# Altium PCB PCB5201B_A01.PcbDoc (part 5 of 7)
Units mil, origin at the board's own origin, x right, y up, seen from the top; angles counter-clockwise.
Board outline 4527.56 x 2362.2 mil, 6 copper layers (Top Layer, GND Layer 2, Signal Layer 3, Signal Layer 4, VCC Layer 5, Bottom Layer), stack 61.221 mil thick; 361 components, 250 nets, 1223 pads, 1068 vias.
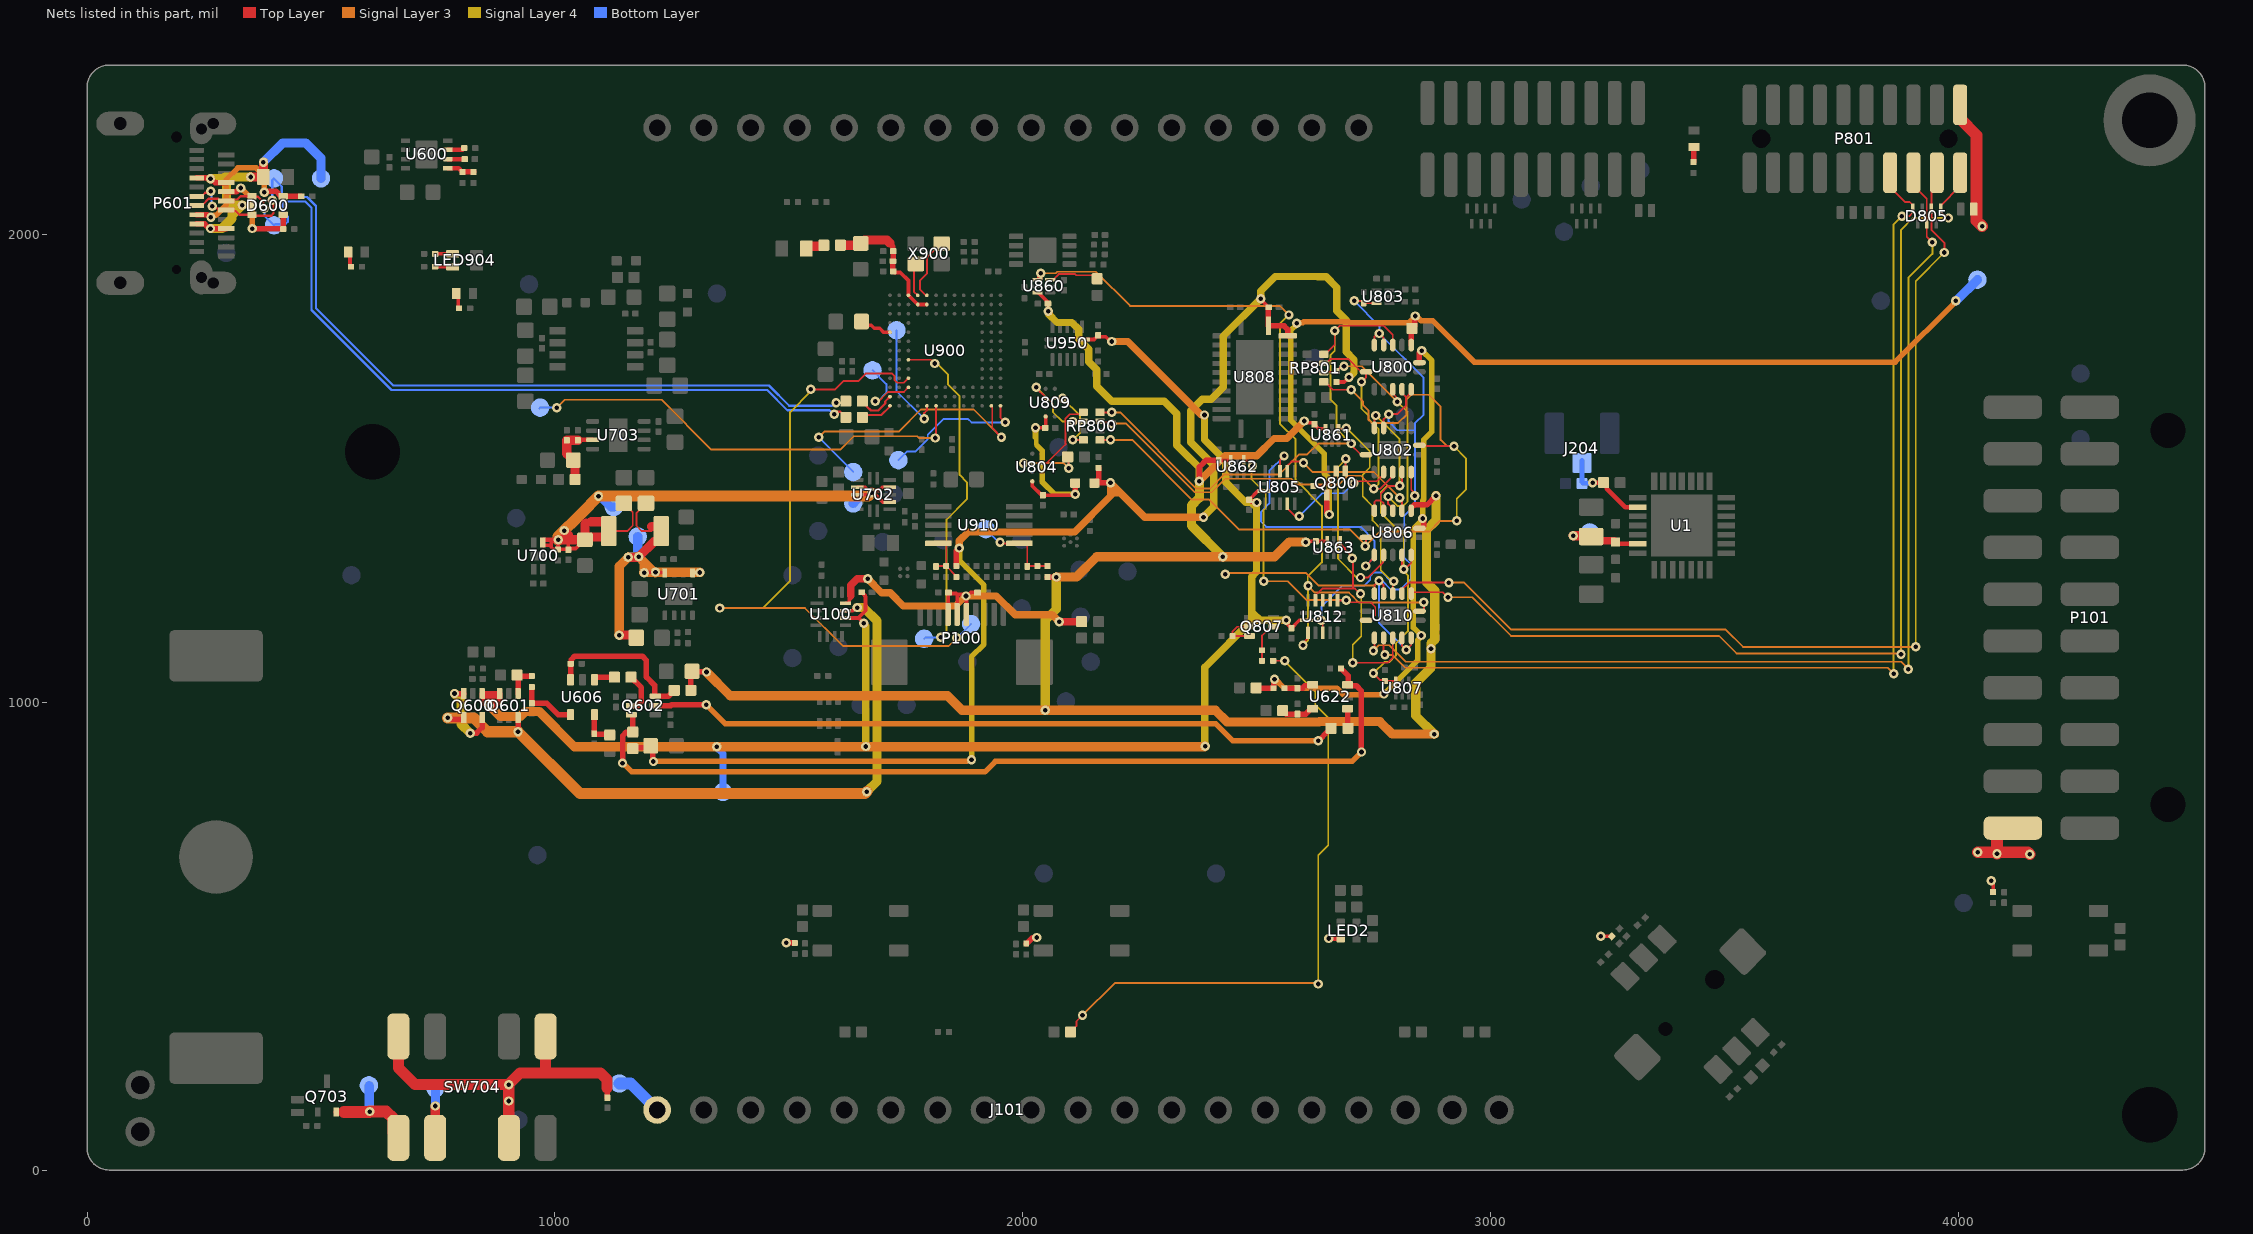
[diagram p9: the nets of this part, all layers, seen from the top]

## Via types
v1: diameter 20, hole 9.84, Top Layer to Bottom Layer, tented both sides, 1068 vias

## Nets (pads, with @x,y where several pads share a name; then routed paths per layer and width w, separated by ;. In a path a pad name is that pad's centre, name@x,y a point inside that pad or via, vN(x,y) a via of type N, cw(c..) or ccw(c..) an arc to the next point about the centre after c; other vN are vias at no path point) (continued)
N17517496: U802.10 U805.4 | length 264.9
  Top Layer w3.94: U805.4@2565.94,1424.61 2565.94,1414.37 2582.68,1397.64 v1(2591.54,1397.64) ; v1(2707.68,1468.5) 2711.61,1472.44 2747.08,1472.44 2756.86,1472.44 2771.65,1487.23 U802.10@2771.65,1492.13
  Bottom Layer w3.94: v1(2591.54,1397.64) 2640.75,1446.85 2686.02,1446.85 v1(2707.68,1468.5)
N17517567: R808.1 U802.6 U802.12 U806.5 U806.6 U806.12 U806.13 U807.3 | length 970.2
  Top Layer w3.94: v1(2750,1062.01) 2764.71,1047.3 2772.58,1047.3 R808.1@2774.61,1045.28 ; U806.6@2751.97,1409.45 2751.97,1428.15 2754.92,1431.1 2765.75,1431.1 ; U802.6@2751.97,1586.61 2752.43,1587.07 2752.43,1610.69 v1(2754.92,1613.19) ; U806.5@2771.65,1409.45 2771.65,1425.2 2765.75,1431.1 ; R808.1@2774.61,1044.29 2775.59,1045.28 2796.77,1045.28 U807.3@2797.76,1044.29 ; U806.12@2811.02,1314.96 2811.02,1292.73 2814.96,1288.8 v1(2814.96,1284.45) ; U802.12@2811.02,1492.13 2811.02,1467.52 v1(2806.1,1462.6) 2782.26,1462.6 2765.75,1446.09 2765.75,1431.1 ; v1@2814.96,1282.48 2830.71,1298.23 U806.13@2830.71,1314.96
  Signal Layer 4 w3.94: v1@2750,1063.98 2751.97,1063.98 2773.9,1085.91 2783.74,1085.91 2798.23,1100.39 2798.23,1125.98 2823.82,1151.57 2823.82,1271.24 2814.96,1280.1 v1(2814.96,1284.45) 2814.96,1356.3 2765.75,1405.51 2765.75,1448.82 2779.53,1462.6 v1(2806.1,1462.6) 2806.1,1562.01 v1(2754.92,1613.19)
N17517613: RP800.5 U804.C1 | length 166.8
  Top Layer w3.94: U804.C1@2040.35,1511.81 2052.17,1511.81 2091.54,1551.18 2091.54,1606.3 2091.82,1606.58 2091.82,1606.8 2100.88,1615.86 2125.71,1615.86 RP800.5@2129.92,1620.08
N17517626: RP800.6 U809.C2 | length 172.2
  Top Layer w3.94: v1(2029.37,1673.41) 2029.37,1671.82 2049.21,1651.98 U809.C2@2049.21,1650.59 ; v1(2107.28,1600.39) RP800.6@2129.92,1600.39
  Signal Layer 4 w3.94: v1(2029.37,1673.41) 2064.96,1637.83 2064.96,1620.08 2084.65,1600.39 v1(2107.28,1600.39)
N17517692: RP800.8 U809.C1 | length 150.2
  Top Layer w3.94: U809.C1@2068.9,1650.59 2069.11,1650.38 2084.97,1650.38 v1(2085.19,1650.16) ; v1(2107.28,1561.02) RP800.8@2129.92,1561.02
  Signal Layer 4 w3.94: v1(2085.19,1650.16) 2122.75,1612.6 2122.75,1576.49 v1(2107.28,1561.02)
N17517773: U805.9 U806.3 | length 317.4
  Top Layer w3.94: U805.9@2565.94,1494.29 2565.94,1505.91 2574.8,1514.76 2597.44,1514.76 v1(2600.39,1511.81) ; v1(2806.1,1437.01) 2811.02,1432.09 U806.3@2811.02,1409.45
  Signal Layer 3 w3.94: v1(2600.39,1511.81) 2620.08,1492.13 2751.21,1492.13 2806.1,1437.23 v1(2806.1,1437.01)
N17517791: U805.10 U806.9 | length 549.3
  Top Layer w3.94: U805.10@2550.2,1494.29 2550.2,1517.72 2558.94,1526.46 v1(2558.94,1526.69) ; v1(2733.27,1291.34) 2751.97,1310.04 U806.9@2751.97,1314.96
  Bottom Layer w3.94: v1(2558.94,1526.69) 2558.94,1526.46 2527.56,1495.08 2527.56,1425.2 2509.84,1407.48 2509.84,1385.83 2520.67,1375 2722.44,1375 2751.97,1345.47 2751.97,1310.04 v1(2733.27,1291.34)
N17517812: Q800.1 U806.10 | length 389.8
  Top Layer w3.94: Q800.1@2689.96,1494.09 2690.3,1494.43 2690.3,1520.02 v1(2690.83,1520.56) ; v1(2722.44,1266.73) 2738.19,1266.73 2770.68,1299.23 2770.68,1313.99 U806.10@2771.65,1314.96
  Signal Layer 4 w3.94: v1(2690.83,1520.56) 2690.83,1519.57 2674.21,1502.95 2674.21,1307.31 2714.79,1266.73 v1(2722.44,1266.73)
N17517960: R810.1 U804.C2 | length 147.4
  Top Layer w3.94: v1(2001.97,1511.32) 2002.46,1511.81 U804.C2@2020.67,1511.81 ; R810.1@2096.46,1524.61 2098.43,1522.64 v1(2098.43,1500)
  Signal Layer 3 w3.94: v1(2001.97,1511.32) 2088.09,1511.32 2099.41,1500 v1(2098.43,1500)
N17517966: Q800.2 R815.1 | length 65.8
  Top Layer w3.94: R815.1@2621.66,1462.29 2645.36,1462.29 2670.28,1487.2 Q800.2@2670.28,1494.09
N17518258: C804.1 C810.1 L801.2 U804.A2 U809.A2 | length 382.4
  Top Layer w7.87: U804.A2@2020.67,1472.44 2020.67,1462.6 2040.35,1442.91 C804.1@2043.31,1442.91 2110.24,1442.91 v1(2112.2,1444.88) ; v1(2027.56,1586.61) C810.1@2048.23,1586.61 2049.21,1587.6 U809.A2@2049.21,1611.22
  Top Layer w11.81: v1(2112.2,1444.88) L801.2@2112.21,1468.5
  Signal Layer 4 w9.84: 2027.56,1566.93 2029.53,1564.96 2029.53,1550.2 2031.5,1548.23
  Signal Layer 4 w11.81: 2027.56,1566.93 v1(2027.56,1586.61) ; 2031.5,1548.23 2042.32,1537.4 2042.32,1470.47 2067.91,1444.88 v1(2112.2,1444.88)
N17535327: U810.1 U812.1 U860.4 | length 1677.4
  Top Layer w3.94: U860.4@2031.5,1903.54 U860.4@2034.45,1903.54 ; v1(2599.41,1122.05) 2599.41,1126.97 2610.24,1137.8 U812.1@2610.24,1148.23 ; U810.1@2848.43,1194.88 2849.41,1195.87 2856.3,1195.87 2858.27,1197.83 2858.25,1212.9 v1(2857.56,1213.58)
  Top Layer w7.87: U860.4@2034.45,1903.54 U860.4@2036.42,1905.51
  Top Layer w11.81: U860.4@2036.42,1905.51 2036.42,1912.68 2039.13,1915.39 v1(2039.13,1917.6)
  Signal Layer 3 w3.94: v1(2039.13,1917.6) 2039.57,1917.16 2070.4,1917.16 2073.79,1920.56 2156.69,1920.56 2229.81,1847.44 2550.2,1847.44 2569.38,1828.26 v1(2569.38,1828.12) ; v1(2610.24,1249.02) 2624.72,1234.53 2697.78,1234.53 2708.94,1223.37 2708.94,1222.92 2718,1213.86 2718.45,1213.86 2718.73,1213.58 v1(2857.56,1213.58)
  Signal Layer 4 w3.94: v1(2569.38,1828.12) 2550.2,1808.94 2550.2,1595.47 2583.66,1562.01 2583.66,1475.39 2639.76,1419.29 2639.76,1299.21 2609.74,1269.19 2609.74,1249.51 v1(2610.24,1249.02) 2610.24,1132.87 v1(2599.41,1122.05)
N17535335: R882.1 U860.3 | length 109.5
  Top Layer w3.94: U860.3@2059.06,1903.54 2064.96,1903.54 2076.97,1915.55 2112.19,1915.55 2114.75,1912.99 2151.97,1912.99 R882.1@2159.45,1905.51
N17535359: U810.4 U812.3 U861.4 | length 686.4
  Top Layer w3.94: v1(2638.78,1175.2) 2641.73,1172.24 U812.3@2641.73,1148.23 ; U861.4@2675.2,1584.65 2693.9,1584.65 v1@2694.88,1585.63 ; U810.4@2791.34,1232.28 2791.34,1254.92 2793.31,1256.89 v1(2793.31,1258.86)
  Signal Layer 4 w3.94: v1(2691.93,1585.63) 2692.91,1585.63 2742.13,1536.42 2742.13,1501.97 2727.08,1486.93 2727.08,1440.24 2748.03,1419.29 2748.03,1388.78 2765.75,1371.06 2765.75,1282.48 2789.37,1258.86 v1(2793.31,1258.86)
  Bottom Layer w3.94: v1(2638.78,1175.2) 2638.78,1204.72 2683.07,1249.02 2730.31,1249.02 2743.11,1261.81 2743.11,1269.69 2750.98,1277.56 2768.7,1277.56 2787.4,1258.86 v1(2793.31,1258.86)
N17535385: U810.8 U812.8 U862.4 | length 608.4
  Top Layer w3.94: U862.4@2472.44,1517.72 2473.75,1517.72 2474.41,1517.06 2480.22,1517.06 v1(2491.47,1505.81) ; U812.8@2673.23,1217.91 2691.34,1217.91 v1(2691.93,1218.5) 2696.57,1213.86 2743.81,1213.86 2753.94,1203.74 2753.94,1186.02 2743.11,1175.2 U810.8@2734.25,1175.2
  Signal Layer 3 w3.94: v1(2515.75,1258.86) 2566.93,1258.86 2607.28,1218.5 v1(2691.93,1218.5)
  Signal Layer 4 w3.94: v1(2491.47,1505.81) 2489.17,1503.51 2489.17,1477.36 2519.68,1446.85 2519.68,1415.35 2514.76,1410.43 v1@2514.76,1258.86
N17535407: U810.11 U812.11 U863.4 | length 518.7
  Top Layer w3.94: U812.11@2625.98,1217.91 2625.98,1228.35 2640.75,1243.11 2706.41,1243.11 ; U863.4@2679.13,1344.49 2679.13,1339.58 2688.98,1329.74 2688.98,1326.77 2704.72,1311.02 v1(2704.72,1308.07) 2706.41,1306.38 2706.41,1243.11 ; v1@2705.63,1084.65 2780.51,1084.65 2791.34,1095.47 U810.11@2791.34,1137.8 ; v1(2722.44,1232.28) 2721.46,1232.28 2710.63,1243.11 2706.41,1243.11
  Signal Layer 4 w3.94: v1(2705.71,1084.65) 2705.71,1123.03 2724.13,1141.45 2724.13,1229.05 2722.44,1230.74 v1(2722.44,1232.28)
N17535812: Q807.5 Q807.6 R838.1 | length 86.9
  Top Layer w3.94: Q807.6@2485.24,1141.73 2485.16,1141.66 2448.93,1141.66 R838.1@2448.86,1141.59 2448.86,1151.62 2458.66,1161.42 Q807.5@2485.24,1161.42
N17535874: Q807.2 R839.2 R841.1 | length 86.5
  Top Layer w3.94: R841.1@2511.98,1088.65 2511.89,1088.73 R839.2@2511.81,1111.22 R839.2@2511.81,1111.22 2511.81,1142.72 2530.51,1161.42 Q807.2@2536.42,1161.42
N17542071: R601.1 R602.2 U600.5 | length 58.4
  Top Layer w9.84: U600.5@770.95,2141.63 794.58,2141.63 R601.1@802.45,2133.76
  Top Layer w11.81: R601.1@802.45,2133.76 R602.2@826.07,2133.76
N17542108: R600.1 U600.7 | length 37.1
  Top Layer w9.84: U600.7@770.95,2181 802.45,2181 R600.1@806.39,2184.94
N17542152: C602.1 U600.6 | length 36.4
  Top Layer w9.84: U600.6@770.95,2161.32 C602.1@807.37,2161.32
N17542390: Q602.6 R674.1 R675.1 U606.3 | length 338.4
  Top Layer w11.81: U606.3@1033.46,1048.23 1033.67,1048.43 1033.67,1082.07 R674.1@1033.87,1082.27 1034.27,1082.27 1034.66,1082.67 1034.66,1090.81 1042.27,1098.41 1187.02,1098.41 1195.87,1089.57 1195.87,1054.07 1213.58,1036.35 Q602.6@1213.58,1015.75 ; Q602.6@1214.57,1012.8 1242.42,1012.8 R675.1@1255.21,1025.59
N17542428: Q602.2 R679.2 | length 86.7
  Top Layer w11.81: R679.2@1162.8,1053.59 1185.04,1031.34 1185.04,1001.01 1177.14,993.11 Q602.2@1163.39,993.11
N17542505: Q601.4 R628.1 R672.2 | length 69.7
  Top Layer w11.81: R628.1@919.29,1058.07 R628.1@921.26,1056.1 ; Q601.4@921.26,1018.7 R628.1@921.26,1056.1 ; R672.2@950.79,1056.1 R628.1@921.26,1056.1
N17542511: C621.1 R672.1 U606.4 | length 132.2
  Top Layer w11.81: R672.1@950.79,1032.48 C621.1@950.79,998.03 982.28,998.03 1006.89,973.42 U606.4@1033.46,973.42 U606.4@1033.46,978.35
N17542554: R679.1 U606.1 | length 46.9
  Top Layer w11.81: U606.1@1084.65,1048.23 1084.65,1051.62 1086.62,1053.59 R679.1@1127.36,1053.59
N17542610: C660.1 R681.1 U606.5 | length 76.2
  Top Layer w11.81: U606.5@1085.63,971.46 1084.4,970.22 1084.4,932.72 C660.1@1084.15,932.47 1084.15,931.68 1084.54,931.29 1117.31,931.29 R681.1@1119.09,933.07
N17542702: Q600.3 Q600.6 | length 170.3
  Top Layer w11.81: v1(785.43,1018.7) Q600.6@805.12,1018.7 ; v1(818.9,934.06) 832.68,934.06 844.49,945.87 Q600.3@844.49,967.52
  Signal Layer 4 w19.68: v1(785.43,1018.7) 799.21,1004.92 799.21,953.74 v1(818.9,934.06)
N17542835: Q602.3 R687.1 R688.1 U622.3 | length 1935.2
  Top Layer w11.81: v1(1144.68,870.08) 1144.68,928.12 1152.59,936.02 1166.21,936.02 R687.1@1166.51,936.33 ; Q602.3@1163.39,973.43 1166.34,973.43 R687.1@1166.34,939.96 ; R688.1@2680.56,1072.15 2680.96,1072.15 2695.87,1057.24 U622.3@2695.87,1037.4 ; U622.3@2691.93,1038.39 2694.53,1035.79 2713.23,1035.79 2724.41,1024.61 v1(2724.41,893.7)
  Signal Layer 3 w11.81: v1(1144.68,870.08) 1145.67,870.08 1164.45,851.29 1919.21,851.29 1941.65,873.74 2590.83,873.74 2704.44,873.74 v1(2724.41,893.7)
N17542861: Q602.5 R686.2 | length 1489.8
  Top Layer w11.81: Q602.5@1214.57,993.11 1247.96,993.11 1249.74,994.9 v1(1323.52,994.9) ; v1(2632.18,917.4) 2653.14,938.36 2653.87,938.36 2657.48,941.97 R686.2@2657.48,945.87
  Signal Layer 3 w11.81: v1(1323.52,994.9) 1364.68,953.74 2413.39,953.74 2449.72,917.4 v1(2632.18,917.4)
N17542916: C653.1 R629.1 U622.4 | length 69.1
  Top Layer w3.94: U622.4@2620.08,1037.4 U622.4@2624.02,1037.4
  Top Layer w11.81: R629.1@2559.79,1030.04 2585.16,1030.04 C653.1@2586.61,1031.5 ; C653.1@2585.63,1029.53 2586.61,1030.51 2598.43,1030.51 2603.35,1035.43 2618.11,1035.43 U622.4@2620.08,1037.4
N17542947: R686.1 U622.1 | length 39.8
  Top Layer w11.81: U622.1@2694.88,986.22 2695.04,986.06 2695.04,947.67 R686.1@2695.87,946.85
N17542995: C652.1 R690.1 U622.5 | length 72
  Top Layer w11.81: R690.1@2555.95,982.05 2563.16,974.85 2605.11,974.85 2610.24,979.98 2610.24,980.31 2616.14,986.22 U622.5@2620.08,986.22
N17547129: TPJ909.1 U900.C11 | length 178.9
  Top Layer w3.94: v1(1685.04,1643.7) 1687.91,1640.83 1689.06,1640.83 1711.61,1663.39 1746.06,1663.39 U900.C11@1755.91,1673.23
  Bottom Layer w3.94: TPJ909.1@1679.19,1709.73 1708.66,1680.26 1708.66,1661.42 1690.94,1643.7 v1(1685.04,1643.7) v1@1685.04,1641.73
N17547147: TPJ910.1 U900.D11 | length 1432.9
  Top Layer w3.94: v1(1547.38,1668.99) 1547.78,1668.59 1598.49,1668.59 1616.62,1686.73 1648.34,1686.73 1664.37,1702.76 1721.01,1702.76 1726.38,1697.39 1726.38,1688.44 1731.75,1683.07 1746.06,1683.07 U900.D11@1755.91,1692.91
  Signal Layer 3 w3.94: v1(1352.66,1201.44) 1534.78,1201.44 1616.14,1120.08 1841.54,1120.08 v1(1859.25,1137.8)
  Signal Layer 4 w3.94: v1(1352.66,1201.44) 1444.55,1201.44 1502.95,1259.84 1502.95,1620.52 1547.38,1664.95 v1(1547.38,1668.99)
  Bottom Layer w3.94: v1(1859.25,1137.8) 1860.35,1137.8 TPJ910.1@1889.89,1167.33
N17547174: TPJ911.1 U900.F11 | length 735.6
  Top Layer w3.94: U900.F11@1755.91,1732.28 1804.13,1732.28 v1(1812.01,1724.41)
  Signal Layer 4 w3.94: v1(1812.01,1724.41) 1815.94,1724.41 1840.55,1699.8 1840.55,1679.13 1865.16,1654.53 1865.16,1486.22 1880.91,1470.47 1880.91,1434.06 1837.6,1390.75 1837.6,1151.57 v1(1824.8,1138.78)
  Bottom Layer w3.94: TPJ911.1@1789.49,1135.83 1792.43,1138.78 v1(1824.8,1138.78)
N17547291: TPJ900.1 U900.A2 | length 621
  Top Layer w3.94: U900.A2@1933.07,1633.86 1933.07,1632.79 1935.04,1630.82 1935.04,1586.61 v1(1954.72,1566.93)
  Signal Layer 3 w3.94: v1(1563.98,1566.93) 1575.79,1578.74 1735.24,1578.74 1782.48,1625.98 1895.67,1625.98 v1(1954.72,1566.93)
  Bottom Layer w3.94: v1(1563.98,1566.93) 1637.89,1493.02 TPJ900.1@1637.89,1492.13
N17547297: TPJ901.1 U900.A1 | length 312.6
  Top Layer w3.94: U900.A1@1952.76,1633.86 1952.76,1608.27 v1(1962.6,1598.43)
  Bottom Layer w3.94: TPJ901.1@1734.39,1517.73 1753.07,1536.42 1771.65,1536.42 1797.24,1562.01 1797.24,1571.85 1830.71,1605.32 1883.86,1605.32 1890.75,1598.43 v1(1962.6,1598.43)
N17547385: TPJ908.1 U900.A9 | length 243.5
  Top Layer w3.94: v1(1789.37,1606.3) 1789.37,1618.11 1795.28,1624.02 U900.A9@1795.28,1633.86
  Bottom Layer w3.94: TPJ908.1@1730.39,1795.33 1730.39,1665.28 v1(1789.37,1606.3)
N17547395: TPJ902.1 U900.A8 | length 981.3
  Top Layer w3.94: v1(1812.99,1564.96) 1814.96,1566.93 U900.A8@1814.96,1633.86
  Signal Layer 3 w3.94: v1(1003.94,1629.92) 1020.67,1646.65 1228.35,1646.65 1334.65,1540.35 1610.24,1540.35 1638.78,1568.9 1774.61,1568.9 1778.54,1564.96 v1(1812.99,1564.96)
  Bottom Layer w3.94: TPJ902.1@966.58,1628 TPJ902.1@968.5,1629.92 v1(1003.94,1629.92)
N17547487: R902.2 U900.B13 | length 83.6
  Top Layer w4.72: R902.2@1657.48,1643.7 1666.93,1634.25 1666.93,1632.33 1675.63,1623.62 1691.28,1623.62 1706.3,1638.64 1706.3,1643.31 U900.B13@1716.54,1653.54
N17547515: R904.2 U900.A13 | length 69.9
  Top Layer w4.72: R904.2@1657.48,1609.25 1662.4,1614.17 1697.96,1614.17 1715.93,1632.14 1715.93,1633.26 U900.A13@1716.54,1633.86
N17547530: U900.N9 X900.3 | length 137.8
  Top Layer w3.94: U900.N9@1795.28,1870.08 1793.31,1870.08 1780.51,1882.87 1780.51,1901.57 1795.28,1916.34 1795.28,1950.79 1824.8,1980.31 X900.3@1826.77,1980.31
N17547541: U900.N10 X900.1 | length 67.9
  Top Layer w3.94: X900.1@1771.65,1933.07 1767.72,1929.13 1767.72,1877.95 U900.N10@1775.59,1870.08
N17547732: LED903.2 R912.2 | length 33.9
  Top Layer w7.87: LED903.2@789.37,1874.02 793.31,1870.08 793.31,1844.49 R912.2@795.28,1842.52
N17547880: C900.1 U900.J13 | length 68.8
  Top Layer w7.87: C900.1@1655.51,1810.04 1659.45,1806.1 1676.18,1806.1 1682.79,1799.49 1694.46,1799.49 1702.62,1791.34 U900.J13@1716.54,1791.34
N17548050: C903.1 C904.1 C905.1 C906.1 R130.2 U900.M9 U900.M10 U900.N11 | length 297.6
  Top Layer w7.87: C904.1@1723.24,1921.35 1725.6,1918.98 1738.5,1918.98 1755.91,1901.57 U900.N11@1755.91,1870.08 U900.M10@1775.59,1850.39 U900.M9@1795.28,1850.39
  Top Layer w11.81: 1706.69,1988.19 1708.5,1988.19 ; 1715.47,1981.22 1722.44,1974.25 1722.44,1964.82 1722.83,1964.42 C906.1@1723.33,1964.42 1723.33,1943.37 1722.93,1942.98 C905.1@1722.85,1942.98 1722.85,1921.74 1723.24,1921.35 C904.1@1723.33,1921.35
  Top Layer w19.68: R130.2@1610.41,1977.14 1650.01,1977.14 C903.1@1653.79,1980.91 ; C903.1@1652.27,1979.04 C903.1@1656.5,1983.27 ; C903.1@1657.48,1984.25 1661.42,1988.19 1706.69,1988.19 ; 1708.5,1988.19 1709.86,1988.19 1716.15,1981.9
N17548152: L900.2 R130.1 | length 35.9
  Top Layer w19.68: L900.2@1541.97,1970.21 1546.92,1975.17 1573.01,1975.17 R130.1@1574.97,1977.14
N17559567: LED904.2 R920.2 | length 37.4
  Top Layer w7.87: R920.2@744.09,1958.66 LED904.2@781.5,1958.66
N17559569: LED904.1 R919.2 | length 37.4
  Top Layer w7.87: R919.2@744.09,1931.1 LED904.1@781.5,1931.1
N17559571: LED900.1 R900.2 | length 32.1
  Top Layer w11.81: R900.2@3434.43,2155.13 3434.74,2155.43 3434.74,2186.71 LED900.1@3435.04,2187.01
N17559573: LED901.1 R903.2 | length 33.9
  Top Layer w7.87: LED901.1@558.07,1962.6 562.01,1958.66 562.01,1933.07 R903.2@563.98,1931.1
N17564018: Q703.2 SW704.8 TP156.1 | length 229.8
  Top Layer w11.81: Q703.2@532.48,124.02 549.21,124.02
  Top Layer w25: 549.21,124.02 v1@603.35,124.02 ; v1(604.33,125) 639.59,125 654.23,110.36 654.23,80.02 SW704.8@665.35,68.9
  Bottom Layer w11.81: TP156.1@602.36,181.1 TP156.1@603.35,180.12 ; v1@603.35,125.98 v1(604.33,125)
  Bottom Layer w19.68: v1@603.35,125.98 TP156.1@603.35,180.12
N17564406: SW704.7 TP704.1 | length 102.8
  Top Layer w19.68: SW704.7@744.09,68.9 v1(744.09,136.81)
  Bottom Layer w19.68: TP704.1@744.5,174.4 745.08,173.82 v1@745.08,139.76
SI_HEADER_ENABLE: R807.1 U800.5 U800.6 U800.12 U800.13 U802.5 U802.13 U803.3 U810.5 U810.6 U810.12 U810.13 | length 1788.8
  Top Layer w3.94: v1(2708.66,1858.27) 2708.86,1858.07 2725,1858.07 2729.33,1853.74 R807.1@2729.33,1853.35 U803.3@2756.89,1853.35 ; U810.6@2751.97,1232.28 2751.97,1250 v1(2761.81,1259.84) 2771.65,1250 U810.5@2771.65,1232.28 ; U800.6@2751.97,1763.78 2751.97,1781.5 2758.86,1788.39 v1(2762.8,1788.39) 2771.65,1779.53 U800.5@2771.65,1763.78 ; U802.5@2771.65,1586.61 2771.65,1605.32 v1(2782.48,1616.14) 2801.18,1616.14 2819.88,1634.84 2819.88,1652.56 ; U810.12@2811.02,1137.8 2811.02,1121.06 v1(2819.88,1112.2) 2830.71,1123.03 U810.13@2830.71,1137.8 ; U800.12@2811.02,1669.29 2811.02,1661.42 2819.88,1652.56 ; U800.13@2829.72,1671.26 U800.13@2831.69,1669.29 ; U802.13@2830.71,1492.13 2830.71,1454.15 2837.6,1447.26 v1@2837.6,1441.93 ; U800.13@2830.71,1669.29 2830.71,1663.39 2819.88,1652.56
  Signal Layer 3 w3.94: v1@2435.04,1276.57 2605.32,1276.57 2631.89,1250 2751.97,1250 v1(2761.81,1259.84)
  Bottom Layer w3.94: v1(2708.66,1858.27) 2762.64,1804.29 2762.64,1788.23 v1@2759.84,1785.43 ; v1(2762.8,1788.39) 2857.28,1693.9 2857.28,1615.16 2838.58,1596.46 2838.58,1581.69 ; v1(2782.48,1616.14) 2782.48,1600.39 2801.18,1581.69 2838.58,1581.69 ; v1(2819.88,1112.2) 2761.81,1170.28 v1(2761.81,1259.84) 2768.7,1259.84 2787.4,1241.14 2807.09,1241.14 2830.43,1264.48 2830.43,1294.57 2815.94,1309.06 2815.94,1398.62 2838.58,1421.26 v1(2838.58,1441.93) 2838.58,1581.69
  other v1: 2433.07,1273.62
SI_VCOM_CTS: D805.4 P801.8 U810.10 | length 2265.8
  Top Layer w3.94: U810.10@2771.65,1137.8 2771.65,1104.33 v1(2774.61,1101.38) ; P801.8@3854.53,2132.22 3854.53,2101.18 3885.83,2069.88 3896.06,2069.88 3903.54,2062.4 3903.54,2047.24 3895.67,2039.37 v1(3879.92,2039.37)
  Signal Layer 3 w3.94: v1(2774.61,1101.38) 2790.35,1101.38 2817.91,1073.82 3849.41,1073.82 v1(3862.2,1061.02)
  Signal Layer 4 w3.94: v1(3862.2,1061.02) 3862.2,1867.13 3862.2,2021.65 v1(3879.92,2039.37)
SI_VCOM_RTS: D805.6 P801.6 U810.9 | length 2297.4
  Top Layer w3.94: v1(2750,1110.24) 2751.97,1112.21 U810.9@2751.97,1137.8 ; P801.6@3904.53,2132.22 3904.53,2105.31 3933.07,2076.77 D805.6@3933.07,2023.03 3933.07,1995.08 v1(3944.88,1983.27)
  Signal Layer 3 w3.94: v1(2750,1110.24) 2761.81,1122.05 2783.46,1122.05 2818.9,1086.61 3877.95,1086.61 v1(3893.7,1070.87)
  Signal Layer 4 w3.94: v1(3893.7,1070.87) 3893.7,1907.48 3944.88,1958.66 v1(3944.88,1983.27)
SI_VCOM_RXD: D805.1 P801.2 U810.2 | length 2246.7
  Top Layer w3.94: U810.2@2830.71,1232.28 2830.71,1235.24 2898.62,1235.24 v1(2909.45,1224.41) ; v1(3979.33,2035.43) 3976.38,2035.43 3962.6,2049.21 D805.1@3962.6,2055.71 3962.6,2062.01 4004.53,2103.94 P801.2@4004.53,2132.22
  Signal Layer 3 w3.94: v1(2909.45,1224.41) 2961.61,1224.41 3044.29,1141.73 3488.92,1141.73 3526.32,1104.33 3876.54,1104.33 v1(3877.95,1102.92)
  Signal Layer 4 w3.94: v1(3877.95,1102.92) 3877.95,1991.29 ; 3877.93,1991.32 3877.93,2004.13 3877.95,2009.84 3903.54,2035.43 v1(3979.33,2035.43)
SI_VCOM_TXD: D805.2 P801.4 U810.3 | length 2225.7
  Top Layer w3.94: U810.3@2811.02,1232.28 2811.02,1240.16 2826.77,1255.91 v1(2911.42,1255.91) ; P801.4@3954.53,2132.22 3942.91,2120.61 D805.2@3942.91,2055.71 3942.91,2009.84 3971.21,1981.54 3971.21,1962.35 v1(3970.47,1961.61)
  Signal Layer 3 w3.94: v1(2911.42,1255.91) 2943.9,1255.91 3044.29,1155.51 3502.95,1155.51 3540.07,1118.39 v1(3909.45,1118.39)
  Signal Layer 4 w3.94: v1(3909.45,1118.39) 3909.45,1900.59 v1(3970.47,1961.61)
TCK_SWCLK: RP800.3 RP801.3 U800.8 U802.11 | length 1123.9
  Top Layer w3.94: RP800.3@2165.35,1600.39 2167.64,1598.11 2187.98,1598.11 v1(2190.27,1595.83) ; RP801.3@2643.7,1724.41 2649.16,1724.41 2659,1734.25 2695.87,1734.25 2723.43,1706.69 U800.8@2734.25,1706.69 2734.25,1694.88 v1@2724.54,1685.17 ; v1(2750.98,1456.69) 2764.74,1456.69 2791.34,1483.3 U802.11@2791.34,1492.13
  Signal Layer 3 w3.94: v1(2190.27,1595.83) 2221.55,1595.83 2368.28,1449.1 2404.24,1449.1 2433.03,1477.88 2574.28,1477.88 2586.61,1465.55 2676.18,1465.55 2694.88,1484.25 2723.43,1484.25 v1(2750.98,1456.69)
  Signal Layer 4 w3.94: v1(2724.54,1685.12) 2724.54,1627.83 2739.17,1613.19 2739.17,1606.3 2760.83,1584.65 2760.83,1466.54 v1(2750.98,1456.69)
TDI: RP800.1 RP801.1 U802.1 U806.8 | length 1610.3
  Top Layer w3.94: RP800.1@2165.35,1561.02 v1(2187.99,1561.02) ; RP801.1@2643.7,1685.04 2646.73,1685.04 2663.46,1668.31 v1(2702.76,1668.31) ; v1@2734.25,1337.6 U806.8@2734.25,1352.36 ; U802.1@2848.43,1549.21 2849.37,1548.27 2921.35,1548.27 v1(2922.29,1547.33)
  Signal Layer 3 w3.94: v1(2187.99,1561.02) 2234.09,1561.02 2361.76,1433.35 2398.65,1433.35 2462.36,1369.64 2699.26,1369.64 2732.28,1336.61 v1(2732.28,1333.66) 2763.78,1365.16 2869.09,1365.16 2891.73,1387.8 v1(2928.15,1387.8) ; v1(2702.76,1668.31) 2727.36,1643.7 2727.36,1635.83 2739.17,1624.02 2739.17,1604.33 2746.06,1597.44 2803.15,1597.44 2820.87,1615.16 2820.87,1647.64 2830.71,1657.48 2868.11,1657.48 2893.7,1631.89 2893.7,1561.02 2906.39,1548.34 2919.18,1548.34 v1@2921.26,1546.26
  Signal Layer 4 w3.94: v1(2922.29,1547.33) 2947.83,1521.78 2947.83,1454.72 2928.15,1435.04 v1(2928.15,1387.8)
TDO_SWO: R801.1 RP801.2 U800.11 U806.4 | length 538.7
  Top Layer w3.94: RP801.2@2643.7,1704.72 2645.53,1706.55 2669.4,1706.55 R801.1@2671.23,1708.38 2671.23,1708.77 2677.89,1715.43 2683.93,1715.43 v1@2686.02,1717.52 ; v1@2684.06,1717.52 v1@2686.02,1717.52 ; v1(2687.01,1718.5) v1@2686.02,1717.52 ; v1(2781.5,1439.96) 2781.5,1424.18 2791.34,1414.34 U806.4@2791.34,1409.45 ; U800.11@2791.34,1669.29 2791.34,1660.43 2801.18,1650.59 v1(2801.18,1642.72)
  Signal Layer 3 w3.94: v1(2687.01,1718.5) 2725.39,1718.5 v1(2801.18,1642.72)
  Signal Layer 4 w3.94: v1(2781.5,1439.96) 2781.5,1439.74 2801.94,1419.29 2812.99,1419.29 2822.83,1429.13 2822.83,1621.06 v1(2801.18,1642.72)
TMS_SWDIO: RP800.4 RP801.4 U800.4 U802.8 | length 1175.7
  Top Layer w3.94: RP800.4@2165.35,1620.08 2165.67,1619.76 v1(2190.77,1619.76) ; RP801.4@2643.7,1744.09 2646.65,1744.09 2667.32,1764.76 v1(2667.32,1794.29) 2678.15,1805.12 2771.65,1805.12 2791.34,1785.43 U800.4@2791.34,1763.78 ; v1(2702.76,1553.15) 2699.8,1553.15 2723.43,1529.53 U802.8@2734.25,1529.53
  Signal Layer 3 w3.94: v1(2190.77,1619.76) 2208.75,1619.76 2371.55,1456.97 2400.98,1456.97 2431.21,1487.2 2549.21,1487.2 2591.82,1529.81 2608.55,1529.81 2631.89,1553.15 v1(2702.76,1553.15)
  Signal Layer 4 w3.94: v1(2667.32,1794.29) 2667.32,1751.97 2658.46,1743.11 2658.46,1646.65 2671.26,1633.86 2671.26,1583.66 2701.77,1553.15 v1(2702.76,1553.15)
UFL_ADC_IN: J204.1 R5.1 R220.2 U1.2 | length 197.5
  Top Layer w9.84: v1(3218.5,1469.49) R5.1@3242.13,1469.49 3249.02,1462.6 3249.02,1456.69 3288.39,1417.32 U1.2@3319.88,1417.32
  Bottom Layer w9.84: J204.1@3195.87,1517.72 3195.87,1470.47 3197.83,1468.5 3217.52,1468.5 v1(3218.5,1469.49)
USB_DM: D600.6 P601.A7 P601.B7 R902.1 TPJ612.1 | length 1850.2
  Top Layer w4.72: P601.B7@234.25,2081.69 244.69,2081.69 252.32,2089.33 261.36,2089.33 v1(264.28,2092.25) ; v1(267.23,2060.52) 270.16,2057.6 276.06,2057.6 278.54,2055.12 294.29,2055.12 299.38,2050.02 318.09,2050.02 325.84,2042.27 D600.6@352.23,2042.27 354.26,2040.24 393.59,2040.24 398.23,2044.88 398.23,2070.66 v1(395.64,2073.25) ; v1(1601.15,1640.03) 1618.38,1640.03 R902.1@1622.05,1643.7
  Bottom Layer w4.72: v1(264.28,2092.25) 265.76,2090.77 265.76,2062 v1(267.23,2060.52) ; v1@395.67,2074.8 395.67,2116.14 TPJ612.1@399.61,2120.08 399.61,2119.14 416.11,2102.64 416.11,2087.83 423.62,2080.31 469.88,2080.31 489.17,2061.02 489.17,1842.52 654.53,1677.17 1457.68,1677.17 1500.98,1633.86 1591.78,1633.86 1597.95,1640.03 v1(1601.15,1640.03)
USB_DP: D600.4 P601.A6 P601.B6 R904.1 TPJ611.1 | length 1825.7
  Top Layer w4.72: P601.B6@234.25,2062.01 237.2,2064.96 248.03,2064.96 259.46,2076.39 280.31,2076.39 284.84,2071.85 P601.A6@297.24,2071.85 300.2,2074.8 321.07,2074.8 327.91,2081.64 D600.4@352.23,2081.64 353.16,2080.71 365.16,2080.71 376.99,2068.87 376.99,2058.05 v1(378.94,2056.1) ; v1(1597.55,1616.03) 1602.5,1620.98 1610.15,1620.98 1610.24,1621.06 R904.1@1622.05,1609.25
  Bottom Layer w4.72: v1(378.94,2056.1) 378.94,2040.35 TPJ611.1@399.61,2019.69 401.96,2022.04 423.61,2022.04 429.13,2027.56 429.13,2038.58 417.52,2050.2 417.52,2068.1 420.28,2070.87 465.97,2070.87 479.72,2057.11 479.72,1838.61 650.61,1667.72 1453.76,1667.72 1497.07,1624.41 1587.2,1624.41 1595.58,1616.03 v1(1597.55,1616.03)
USBC_CC1: D600.1 P601.A5 R621.2 | length 231.8
  Top Layer w11.81: P601.A5@297.24,2091.54 318.9,2091.54 326.77,2099.41 v1(328.74,2099.41) ; v1(353.35,2012.8) 353.94,2012.2 418.9,2012.2 R621.2@419.23,2011.88 ; R621.2@419.29,2011.81 R621.2@419.23,2011.88 ; D600.1@420.28,2042.32 419.23,2041.27 R621.2@419.23,2011.88
  Signal Layer 3 w11.81: v1(328.74,2099.41) 353.35,2074.8 v1(353.35,2012.8) v1@353.35,2009.84
USBC_CC2: D600.3 P601.B5 R620.2 | length 350.1
  Top Layer w11.81: P601.B5@234.25,2042.32 256.88,2042.32 262.48,2036.72 v1(264.69,2036.72) ; v1(378.94,2090.55) 382.22,2087.27 387.6,2092.65 403.68,2092.65 414.69,2081.64 D600.3@419.16,2081.64 456.64,2081.64 R620.2@456.69,2081.69
  Signal Layer 3 w11.81: v1(264.69,2036.72) 266.91,2036.72 271.3,2041.12 275.27,2041.12 297.24,2063.09 297.24,2117.55 322.14,2142.44 361.13,2142.44 378.94,2124.63 v1(378.94,2090.55)
USBC_VBUS: D600.5 L600.1 P601.A4 P601.A9 P601.B4 P601.B9 TPJ613.1 | length 706.9
  Top Layer w11.81: P601.B4@234.25,2022.64 251.33,2022.64 259.61,2014.36 262.21,2014.36 v1(263.78,2012.8) ; P601.B9@234.25,2121.06 254.92,2121.06 255.32,2120.66 262.21,2120.66 v1(263.78,2119.09) ; v1@262.8,2119.09 v1(263.78,2119.09) ; v1@264.76,2012.8 P601.A9@297.24,2012.8 ; P601.A4@297.24,2111.22 273.87,2111.22 266,2119.09 v1(263.78,2119.09) ; v1(331.69,2062.99) 332.21,2062.47 351.71,2062.47 D600.5@352.23,2061.96
  Top Layer w19.68: v1@349.44,2123.06 L600.1@376.78,2123.09 ; L600.1@376.78,2123.09 376.91,2123.21 v1(376.97,2154.53) v1(376.97,2154.53)
  Signal Layer 4 w19.68: v1(263.78,2119.09) 290.63,2119.09 ; v1@267.72,2012.8 288.39,2012.8 309.76,2034.17 309.76,2062.99 ; 309.76,2041.06 v1(331.69,2062.99) ; v1@328.74,2062.99 309.76,2062.99 ; v1(349.41,2123.03) 309.76,2123.03 ; 290.63,2119.09 294.57,2123.03 309.76,2123.03 ; 290.63,2119.09 298.23,2111.5 ; 298.23,2111.5 298.23,2074.52 309.76,2062.99 ; 298.23,2111.5 309.76,2123.03
  Bottom Layer w19.68: v1@377.95,2155.51 418.31,2195.87 467.52,2195.87 500,2163.39 TPJ613.1@500,2120.08
V_SW: C104.1 C800.1 C828.1 C950.1 Q600.4 Q601.6 TPJ608.1 U100.10 U805.14 U812.14 U950.14 | length 3618
  Top Layer w7.87: U100.10@1621.65,1180.12 1649.61,1180.12 v1(1660.43,1169.29) ; 1648.41,1180.12 1664.19,1195.89 1664.19,1225.47 1663.11,1226.55 1663.11,1228.21 1659.56,1231.75 1659.56,1232.82 1657.2,1235.18 C104.1@1656.41,1235.18 ; U950.14@2130.32,1775.59 2152.56,1775.59 2158.27,1781.3 2159.06,1781.3 2161.42,1783.66 C950.1@2161.42,1784.45 2163.23,1782.64 2163.23,1781.85 2163.78,1781.3 2177.59,1781.3 2187.49,1771.41 v1(2190.77,1771.41) ; v1(2500.83,1427.17) 2501.97,1427.17 2500.98,1428.15 2489.17,1428.15 C800.1@2484.25,1433.07 2502.76,1451.57 U805.14@2515.35,1451.57 ; v1(2563.98,1175.2) 2563.98,1169.29 C828.1@2574.8,1158.46 2591.54,1175.2 U812.14@2606.89,1175.2
  Top Layer w11.81: 844.49,1002.95 877.25,1002.95 879.57,1000.63 ; 844.49,1002.95 Q600.4@844.49,1008.86 ; 844.49,1002.95 854.33,993.11 v1(860.24,993.11) 872.05,993.11 879.57,1000.63 ; Q600.4@844.49,1008.86 Q601.6@881.89,1008.86 ; Q600.4@844.49,1008.86 Q600.4@844.49,1018.7 Q601.6@881.89,1018.7 Q601.6@881.89,1008.86 ; 879.57,1000.63 881.89,1002.95 Q601.6@881.89,1008.86
  Signal Layer 3 w15.75: v1(2190.77,1771.41) 2224.66,1771.41 2381.89,1614.17 v1(2388.78,1614.17)
  Signal Layer 3 w19.68: v1(860.24,993.11) 883.86,969.49 926.18,969.49 937.01,980.32 966.54,980.32 1041.68,905.17 1663.94,905.17 1664.22,905.45 v1@1664.27,905.41 ; v1@1664.72,905.17 2388.94,905.17 2390.05,906.27 v1@2390.09,906.23
  Signal Layer 4 w15.75: v1(1660.43,1169.29) 1660.43,1168.14 1664.37,1164.2 v1(1664.37,905.51) ; v1(2388.78,1614.17) 2388.78,1561.02 2434.06,1515.75 2434.06,1470.47 2477.36,1427.17 2489.17,1427.17 ; v1(2390.19,906.33) 2389.76,906.76 2389.76,1074.8 2490.16,1175.2 ; 2493.11,1189.96 2507.87,1175.2 ; v1(2563.98,1175.2) 2507.87,1175.2 ; 2489.17,1427.17 2495,1427.17 v1(2500.83,1427.17) 2500,1426.34 2500,1416.34 ; 2489.17,1427.17 2495,1421.34 2500,1416.34 ; 2490.16,1175.2 2490.16,1189.96 2490.16,1268.7 2500,1278.54 2500,1416.34 ; 2490.16,1175.2 2507.87,1175.2
  Bottom Layer w15.75: v1(1345.78,905.17) 1345.78,904.02 1359.39,890.41 TPJ608.1@1359.39,808.13
VCOM_CTS: U812.9
VCOM_ENABLE: R304.1 R841.2 | length 1342.6
  Top Layer w3.94: R304.1@2102.36,295.28 2115.16,308.07 2115.16,317.91 v1(2127.95,330.71) ; R841.2@2535.6,1088.65 2560.1,1088.65 v1(2560.04,1088.58)
  Signal Layer 3 w3.94: v1(2127.95,330.71) 2196.85,399.61 2629.92,399.61 v1(2631.89,397.64)
  Signal Layer 4 w3.94: v1(2560.04,1088.58) 2573.27,1075.35 2573.34,1075.35 2625.7,1022.98 2625.7,994.31 2653.54,966.47 2653.54,694.49 2631.89,672.84 v1(2631.89,397.64)
VCOM_RTS: U812.10
VCS: C710.1 C714.1 C728.1 R717.2 U703.7 | length 146.5
  Top Layer w9.84: C710.1@1050.2,1561.02 U703.7@1080.71,1561.02
  Top Layer w11.81: C710.1@1049.21,1560.04 C710.1@1050.2,1561.02
  Top Layer w19.68: R717.2@1043.31,1476.38 1043.31,1513.78 C714.1@1039.37,1517.72 1025.59,1531.5 C728.1@1025.59,1560.04 C710.1@1049.21,1560.04
VDISP: C143.1 C144.1 P100.4 P100.5 P100.6 R145.2 U100.12 | length 810.9
  Top Layer w7.87: U100.12@1621.65,1211.61 1629.53,1211.61 1629.53,1219.49 ; 1629.92,1230.32 1629.53,1229.92 1629.53,1219.49 ; 1631.89,1224.41 1631.89,1221.85 1629.53,1219.49 ; P100.4@1840.55,1187.99 1841.02,1188.46 1841.02,1234.34 C143.1@1841.49,1234.81 1843.86,1232.45 1858.1,1232.45 1860.24,1230.32 ; P100.5@1860.24,1187.99 1860.24,1230.32 ; P100.6@1879.92,1187.99 v1@1879.92,1227.34 ; v1@1879.92,1227.36 1878.94,1228.35 v1@1882.49,1228.35 ; C144.1@1903.53,1234.98 1889.12,1234.98 v1@1882.49,1228.35 ; 1860.24,1230.32 1873.02,1230.32 1876,1227.34 v1(1878.91,1227.34) v1@1879.92,1227.34 ; v1@1879.92,1227.34 1881.48,1227.34 v1@1882.49,1228.35
  Top Layer w15.75: 1632.87,1227.36 1632.87,1250 1646.64,1263.76 v1(1668.67,1263.76) ; R145.2@2126.26,1172.53 R145.2@2126.26,1172.53 v1@2078.12,1172.5 ; v1(2078.08,1172.46) v1@2078.12,1172.5
  Signal Layer 3 w15.75: v1(1668.67,1263.76) 1698.3,1234.13 1716.95,1234.13 1745.08,1205.99 1856.41,1205.99 1877.76,1227.34 1943.61,1227.34 1984.09,1186.86 2063.69,1186.86 v1@2077.27,1173.28
VMCU: C1.1 C2.1 C706.1 D808.1 J101.1 LED2.1 P101.2 P801.1 Q600.1 Q601.3 R9.1 R100.2 R101.2 R111.2 SW704.1 SW704.4 SW704.6 TP157.1 TP703.1 U1.6 U100.11 | length 3143.1
  Top Layer w7.87: U100.11@1621.65,1195.87 1636.22,1195.87 1642.86,1202.51 v1(1646.14,1202.51) ; v1(3236.22,500) 3236.7,499.52 R111.2@3259.36,499.52 ; v1(4070.87,618.11) 4074.8,614.17 R9.1@4074.8,594.49
  Top Layer w9.84: C2.1@3269.68,1341.54 3272.64,1338.58 U1.6@3319.88,1338.58
  Top Layer w11.81: v1(770.75,966.58) 770.75,966.46 773.62,963.58 801.18,963.58 Q600.1@805.12,967.52 ; v1(921.26,937.01) Q601.3@921.26,967.52 ; 1111.81,175.2 1111.81,154.92 C706.1@1112.21,154.53 ; v1@1492.13,485.24 1492.78,485.89 1512.63,485.89 R101.2@1512.96,485.56 ; R100.2@2007.87,484.25 2008.86,484.25 2021.65,497.05 v1(2030.51,497.05) ; v1(2654.53,495.08) LED2.1@2680.12,495.08
  Top Layer w15.75: C1.1@3215.55,1354.33 3224.41,1345.47 3264.76,1345.47 C2.1@3267.72,1342.52
  Top Layer w19.68: v1(3177.17,1356.3) 3177.23,1356.24 3208.98,1356.24 C1.1@3211.82,1353.41
  Top Layer w23.62: SW704.4@665.35,285.43 665.35,218.5 700.79,183.07 v1@895.67,183.07 ; v1@900.59,183.07 925.2,207.68 980.32,207.68 ; SW704.1@980.32,285.43 980.32,207.68 ; 1111.81,175.2 1111.81,193.84 1097.97,207.68 980.32,207.68
  Top Layer w25: SW704.6@901.58,68.9 v1(901.57,147.64) v1(901.57,182.09) ; P801.1@4004.53,2277.22 4004.53,2247.44 4039.37,2212.6 ; 4039.31,2211.52 4039.31,2029.36 v1(4051.18,2017.48) ; v1(4042.11,679.69) v1@4083.05,679.69 ; v1(4083.05,676.54) v1@4083.05,679.69 ; P101.2@4116.93,731.1 4095.55,731.1 4083.05,718.6 v1@4083.05,679.69 ; v1(4153.46,675.4) 4149.17,679.69 v1@4083.05,679.69
  Signal Layer 3 w23.62: v1(770.75,966.58) 826.72,966.58 856.3,937.01 v1(921.26,937.01) 1053.47,804.79 1662.66,804.79 v1(1666.99,809.12)
  Signal Layer 4 w11.81: v1(770.75,966.58) v1@772.64,964.7
  Signal Layer 4 w19.68: v1(1646.14,1202.51) 1646.2,1202.45 1660.29,1202.45 1688.98,1173.76 1688.98,831.2 1666.99,809.21 v1(1666.99,809.12)
  Bottom Layer w11.81: v1@3176.85,1357.14 3180.22,1357.14 3181,1357.92 3207.33,1357.92 TP157.1@3212.6,1363.19
  Bottom Layer w25: TP703.1@1137.8,185.04 1161.89,185.04 J101.1@1218.5,128.43
  other v1: 1494.79,486.22
VMCU_BUF: C625.1 C861.1 C863.1 C865.1 C867.1 R630.2 R675.2 U806.2 U860.6 U861.6 U862.6 U863.6 | length 4502.3
  Top Layer w7.87: U860.6@2031.5,1875.98 2033.46,1875.98 2054.13,1855.32 C863.1@2054.13,1852.36 2054.64,1851.86 2054.64,1836.81 v1(2055.15,1836.3) ; C861.1@2419.29,1517.72 U862.6@2444.88,1517.72 ; v1(2602.3,1601.32) 2605.59,1601.32 2609.27,1597.64 2621.65,1597.64 2624.02,1595.28 2624.02,1593.7 2633.07,1584.65 U861.6@2647.64,1584.65 ; v1(2605.31,1342.52) 2607.28,1344.49 C867.1@2626.97,1344.49 U863.6@2651.58,1344.49
  Top Layer w11.81: R675.2@1290.64,1025.59 1290.64,1063.56 C625.1@1293.24,1066.16 1293.93,1065.47 1323.53,1065.47 v1(1324.22,1064.78) ; R630.2@2053.15,1267.72 v1(2071.85,1267.72) ; v1(2377.95,1472.44) 2377.95,1503.13 2392.54,1517.72 C861.1@2419.29,1517.72 ; U806.2@2830.71,1409.45 2830.71,1415.35 2837.6,1422.24 2864.17,1422.24 v1(2883.86,1441.93)
  Signal Layer 3 w15.75: v1(2377.95,1472.44) 2432.7,1527.18 2500.61,1527.18 2537.49,1564.06 2565.05,1564.06 v1(2602.3,1601.32)
  Signal Layer 3 w19.68: v1(1324.22,1064.78) 1374.96,1014.04 1839.3,1014.04 1870.55,982.8 v1@2047.76,982.8 ; v1(2048.23,983.27) v1@2047.76,982.8 ; v1(2071.85,1267.72) 2115.32,1267.72 2158.63,1311.02 v1(2428.15,1311.02) 2538.39,1311.02 2569.88,1342.52 v1(2605.31,1342.52) ; v1(2879.92,932.09) 2790.35,932.09 2763.78,958.66 2634.44,958.66 2633.53,957.75 2437.21,957.75 2412.16,982.8 v1@2047.76,982.8
  Signal Layer 4 w15.75: v1(2055.15,1836.3) 2055.96,1835.49 2055.96,1829.67 2073.62,1812.01 2105.31,1812.01 2120.08,1797.24 2120.08,1776.51 2141.73,1754.86 2141.73,1727.92 2158.46,1711.19 2158.46,1675.56 2190.33,1643.7 2303.15,1643.7 2329.72,1617.13 2329.72,1549.21 2344.49,1534.45 ; 2344.84,1534.8 2377.14,1502.5 2377.14,1473.25 v1(2377.95,1472.44)
  Signal Layer 4 w19.68: v1(2048.23,983.27) 2048.23,1175.62 2071.85,1199.24 v1(2071.85,1267.72) ; v1(2377.95,1472.44) 2377.89,1472.38 2377.89,1437.4 2361.22,1420.73 2361.22,1377.95 v1(2428.15,1311.02) ; v1(2879.92,932.09) 2840.55,971.46 2840.55,1041.34 2873.09,1073.88 2873.09,1126.04 2880.91,1133.86 2880.91,1239.07 2863.19,1256.79 2863.19,1368.11 2883.86,1388.78 v1(2883.86,1441.93)
  other v1: 2873.03,1114.17
VMCU_R: R701.1 R702.2 R709.2 TP700.1 U701.1 U701.4 | length 771.1
  Top Layer w3.94: R709.2@1194.88,1425.2 1174.21,1404.53 1174.21,1377.95 1186.02,1366.14 1207.2,1366.14
  Top Layer w7.87: v1(1191.28,1277.28) 1191.83,1277.84 1214.61,1277.84 v1(1215.16,1278.4) 1216.07,1277.48 1234.33,1277.48 U701.4@1235.24,1276.57 ; U701.1@1294.29,1276.57 1294.78,1277.07 1309.55,1277.07 v1(1310.04,1277.56)
  Top Layer w19.68: v1(1137.8,1143.7) 1137.86,1143.64 1172.77,1143.64 R702.2@1173.85,1142.56 ; v1(1157.07,1310.09) 1157.13,1310.15 1178.54,1310.15 v1(1179.59,1311.11) v1(1179.59,1311.11) ; v1@1179.65,1311.17 1211.98,1343.5 1220.47,1343.5 1227.36,1350.39 1227.36,1352.36 1227.36,1369.09 1220.47,1375.98 1207.2,1375.98
  Signal Layer 3 w19.68: v1(1137.8,1143.7) 1137.8,1290.81 v1(1157.07,1310.09) 1178.56,1310.09 v1(1179.59,1311.11) ; v1@1181.1,1309.06 1190.46,1299.69 ; v1@1189.96,1277.56 1190.24,1277.84 v1@1190.72,1277.84 ; v1(1191.28,1277.28) v1@1190.72,1277.84 ; v1@1208.66,1278.54 1208.66,1281.5 1190.46,1299.69 ; v1@1214.57,1276.57 1215.97,1277.98 1309.62,1277.98 v1(1310.04,1277.56) ; v1(1215.16,1278.4) 1214.61,1277.84 v1@1190.72,1277.84 ; 1190.46,1299.69 1190.46,1278.1 v1@1190.72,1277.84
  Bottom Layer w19.68: v1(1157.07,1310.09) 1157.13,1310.15 1178.54,1310.15 v1(1179.59,1311.11) v1(1179.59,1311.11) 1179.59,1311.2 1177.17,1313.62 TP700.1@1177.17,1354.33
VMCU_S: C700.1 C701.1 R701.2 R710.2 R760.2 TP701.1 TP705.1 U700.3 U702.2 U702.4 U702.9 U702.10 | length 1496.4
  Top Layer w3.94: R701.2@1115.16,1366.14 1154.53,1366.14 1166.34,1377.95 1166.34,1406.5 R710.2@1147.64,1425.2
  Top Layer w7.87: U700.3@975.39,1335.63 990.16,1335.63 ; 996.06,1345.47 992.13,1341.54 992.13,1331.38 996.74,1326.77 1006.69,1326.77 R760.2@1006.81,1326.9 ; v1@1006.81,1344.41 R760.2@1006.81,1326.9 ; C701.1@1026.57,1327.76 1026.57,1326.95 1026.52,1326.9 R760.2@1006.81,1326.9 ; C701.1@1028.89,1326.25 C701.1@1028.89,1326.38 ; 1029.53,1349.41 1028.89,1348.77 1028.89,1347.44 C701.1@1028.89,1326.38 ; C700.1@1059.06,1343.5 1059.06,1343.21 1044.58,1328.74 1031.25,1328.74 C701.1@1028.89,1326.38 ; U702.10@1646.26,1443.9 1673.25,1443.9 v1(1677.25,1447.9) ; U702.9@1646.26,1459.65 1663.39,1459.65 v1@1672.24,1450.79 ; U702.2@1715.95,1428.15 1700.79,1428.15 1681.04,1447.9 v1(1677.25,1447.9) ; U702.4@1715.95,1459.65 1699.8,1459.65 1692.91,1452.76 1682.1,1452.76 v1(1677.25,1447.9)
  Top Layer w9.84: U700.3@975.39,1335.63 974.41,1336.61 U700.3@974.41,1341.54 974.41,1346.46 975.39,1347.44 v1(1006.89,1347.44)
  Top Layer w19.68: v1@1004.09,1347.44 1028.89,1347.44 C700.1@1064.27,1347.44 C700.1@1064.27,1352.41 ; v1(1019.68,1367.13) v1(1019.68,1367.13) 1028.89,1357.84 1028.89,1348.77 ; C700.1@1061.74,1349.87 C700.1@1064.27,1352.41 ; 1065.94,1382.87 1064.27,1381.2 C700.1@1064.27,1352.41 ; 1077.76,1385.83 1108.27,1385.83 1115.16,1378.94 R701.2@1115.16,1366.14 1115.16,1360.24 1108.27,1353.35 1065.22,1353.35 C700.1@1064.27,1352.41
  Signal Layer 3 w23.62: v1(1006.89,1347.44) 1006.89,1354.33 1056.51,1403.95 ; 1056.51,1403.96 1093.49,1440.94 1670.29,1440.94 v1(1677.25,1447.9)
  Bottom Layer w19.68: v1(1093.33,1440.79) 1093.39,1440.73 1097.25,1440.73 1120.66,1417.32 TP701.1@1125.98,1417.32 ; TP705.1@1637.8,1425.2 1660.5,1447.9 v1(1677.25,1447.9)
VMCU_SENSE: C632.1 R630.1 R631.2 TP708.1 U910.6 | length 193.6
  Top Layer w3.94: v1(1951.77,1342.52) 1954.72,1339.57 U910.6@1993.11,1339.57 1994.09,1338.58 2009.84,1338.58 C632.1@2009.84,1290.35 2010.83,1291.34 R631.2@2031.5,1291.34 R630.1@2053.15,1291.34
  Bottom Layer w3.94: TP708.1@1921.26,1370.08 1948.82,1342.52 v1(1951.77,1342.52)
VTARGET: R629.2 R691.1 U800.1 U806.1 | length 1163.2
  Top Layer w11.81: R691.1@2499.1,1030.97 2499.06,1030.93 2499.06,1030.43 R629.2@2535.77,1030.43 ; R629.2@2536.17,1030.04 R629.2@2535.77,1030.43 ; v1(2538.47,1049.29) 2536.96,1047.78 2536.96,1030.43 R629.2@2535.77,1030.43 ; U806.1@2848.43,1372.05 2852.36,1372.05 2857.28,1376.97 2857.28,1388.53 2855.05,1390.77 v1(2855.05,1392.98) ; U800.1@2848.43,1726.38 2848.43,1747.05 v1(2853.35,1751.97)
  Signal Layer 3 w11.81: v1(2538.47,1049.29) 2540.1,1049.29 2558.88,1030.51 2671.7,1030.51 2686.05,1016.17 2771.09,1016.17 v1(2772.64,1017.72)
  Signal Layer 4 w11.81: v1(2772.64,1017.72) 2844.49,1089.57 2844.49,1132.63 2852.36,1140.5 v1(2852.36,1142.72) 2835.63,1159.45 2835.63,1371.35 2855.05,1390.77 v1(2855.05,1392.98) ; v1(2853.35,1751.97) 2875,1730.32 2875,1578.74 2857.99,1561.73 2857.99,1433.89 2855.05,1430.95 2855.05,1395.92 v1@2857.99,1392.98
VTARGET_BUF: C655.1 C806.1 L801.1 R636.2 R687.2 R801.2 R809.2 U808.23 U808.24 | length 3155.7
  Top Layer w7.87: v1(2509.11,1863.05) 2509.11,1861.17 2525.79,1844.49 C806.1@2526.58,1844.49 ; R801.2@2671.23,1684.75 2687.62,1684.75 2697.75,1694.88 v1(2697.83,1694.88)
  Top Layer w11.81: R687.2@1167.56,901.7 1168.83,902.96 1198.98,902.96 C655.1@1204.35,908.33 ; C655.1@1204.88,906.95 1209.15,902.68 1209.15,875.02 v1(1210.71,873.45) ; R636.2@1858.27,1291.34 1858.27,1323.82 v1(1864.17,1329.72) ; L801.1@2153.54,1468.5 L801.1@2153.91,1468.87 ; R809.2@2162.4,1500.98 2162.4,1477.36 L801.1@2153.91,1468.87 ; v1(2187.99,1469) 2187.87,1468.87 L801.1@2153.91,1468.87 ; C806.1@2525.59,1843.5 U808.24@2525.59,1804.92 2559.25,1804.92 2566.73,1797.44 U808.23@2566.73,1783.46 ; v1@2694.88,1694.88 v1@2697.75,1694.88
  Signal Layer 3 w11.81: v1(1210.71,873.45) 1881.44,873.45 1883.39,875.4 1889.18,875.4 v1(1890.75,876.97)
  Signal Layer 3 w15.75: v1(1864.17,1329.72) 1864.82,1330.37 1864.82,1345.13 1883.86,1364.17 2111.22,1364.17 2187.99,1440.95 ; v1(2386.81,1395.67) 2261.32,1395.67 2210.14,1446.85 ; 2187.99,1440.95 v1(2187.99,1469) 2210.14,1446.85 ; 2187.99,1440.95 2195.25,1448.2 2208.29,1448.2 2209.65,1446.85 2210.14,1446.85
  Signal Layer 4 w11.81: v1@1862.2,1327.76 1863.93,1327.76 1865.74,1325.94 1865.74,1302.32 1917.32,1250.74 1917.32,1124.02 1890.75,1097.44 1890.75,880.75 1891.58,879.92 v1@1892.72,879.92
  Signal Layer 4 w15.75: v1(2386.81,1395.67) 2386.81,1396.82 2408.46,1418.47 2408.46,1506.89 2359.25,1556.1 2359.25,1623.03 2383.86,1647.64 2403.54,1647.64 2429.13,1673.23 2429.13,1783.08 v1(2509.11,1863.05) 2509.11,1879.18 2540.35,1910.43 2630.91,1910.43 ; 2630.91,1909.45 2649.11,1909.45 2671.68,1886.87 2671.68,1837.17 2691.93,1816.93 2691.93,1749.38 2708.38,1732.93 2708.38,1704.44 v1@2696.85,1692.91
VTARGET_SENSE: C638.1 R636.1 R637.2 U910.5 | length 124.5
  Top Layer w3.94: C638.1@1814.96,1290.35 1815.95,1291.34 R637.2@1836.61,1291.34 ; U910.5@1819.88,1339.57 U910.5@1836.61,1339.57 ; U910.5@1841.54,1339.57 U910.5@1836.61,1339.57 ; R636.1@1858.27,1267.72 1858.27,1269.69 R637.2@1836.61,1291.34 ; R637.2@1836.61,1291.34 U910.5@1836.61,1339.57
VTREF: Q800.4 R816.2 TPJ817.1 U800.2 | length 2135.6
  Top Layer w11.81: Q800.4@2650.59,1442.91 2650.59,1406.5 v1(2655.51,1401.57) ; U800.2@2830.71,1763.78 2830.71,1797.24 2838,1804.54 2838,1824.22 v1(2839.57,1825.79)
  Signal Layer 3 w11.81: v1(2586.19,1810.26) 2587.75,1811.83 2599.35,1811.83 2601.21,1813.7 2697.13,1813.7 2699.8,1811.02 2824.8,1811.02 v1(2839.57,1825.79) 2841.78,1825.79 2851.9,1815.67 2855.78,1815.67 2855.83,1815.62 2877.29,1815.62 2965.55,1727.36 3865.16,1727.36 3995.08,1857.28 v1(3995.08,1858.27)
  Signal Layer 4 w11.81: v1(2586.19,1810.26) 2586.19,1808.05 2572.83,1794.7 2572.83,1603.35 2644.68,1531.5 2644.68,1489.17 2655.51,1478.35 v1(2655.51,1401.57)
  Bottom Layer w19.68: v1(3995.08,1858.27) 3995.14,1858.33 3996.12,1858.33 TPJ817.1@4041.34,1903.54
pads on no net: D800.5 D801.1 J101.3 J101.4 M2.1 M3.1 P100.11 P100.12 P101.M1 P101.M2 P601.25@70.87,2237.01 P601.26@70.87,1896.85 P601.27@244.09,2225.39 P601.27@269.68,2237.01 P601.28@244.09,1908.46 P601.28@269.69,1896.85 P601.A2 P601.A3 P601.A8 P601.A10 P601.A11 P601.B2 P601.B3 P601.B8 P601.B10 P601.B11 P601.M1 P601.M2 P800.7 P800.11 P800.13 P801.10 P801.12 P801.14 P801.16 P801.18 P801.20 P801.M1 P801.M2 Q100.3 RP800.2 RP800.7 SW105.7 SW105.8 SW105.M1 SW105.M2 U1.4 U1.5 U600.8 U701.8 U800.17 U802.17 U806.17 U808.8 U808.9 U808.10 U810.17 U900.B11 U900.E12 U900.F12 U900.G2 U900.H2 U900.J2 U900.L3 U900.L8 U900.L12 U900.M4 U900.M12 U900.M13 U900.N7 U900.N12 U901.9 U902.C1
